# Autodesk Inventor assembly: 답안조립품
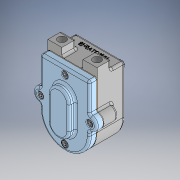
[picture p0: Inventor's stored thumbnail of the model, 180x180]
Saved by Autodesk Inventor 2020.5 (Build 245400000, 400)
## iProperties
Created: 2024-03
Part Number: 답안조립품
Document SubType Name: Assembly
Designer: 1강의실14
Author: 1강의실14
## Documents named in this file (9)
- C:\Users\1강의실14\Desktop\740304V1016\답안조립품.iam
- C:\Users\1강의실14\Desktop\740304V1016\본체.ipt
- C:\Users\1강의실14\Desktop\740304V1016\오일레스 부시.ipt
- C:\Users\1강의실14\Desktop\740304V1016\구동기어.ipt
- C:\Users\1강의실14\Desktop\740304V1016\오일 실 14 25 7.ipt
- C:\Users\1강의실14\Desktop\740304V1016\스퍼기어.ipt
- C:\Users\1강의실14\Desktop\740304V1016\가스켓.ipt
- C:\Users\1강의실14\Desktop\740304V1016\커버.ipt
- C:\Users\1강의실14\Desktop\740304V1016\육각 소켓 머리 볼트 M5x12.ipt
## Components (2 placed, 2 different names)
1. 구동기어:1
2. 가스켓:1
